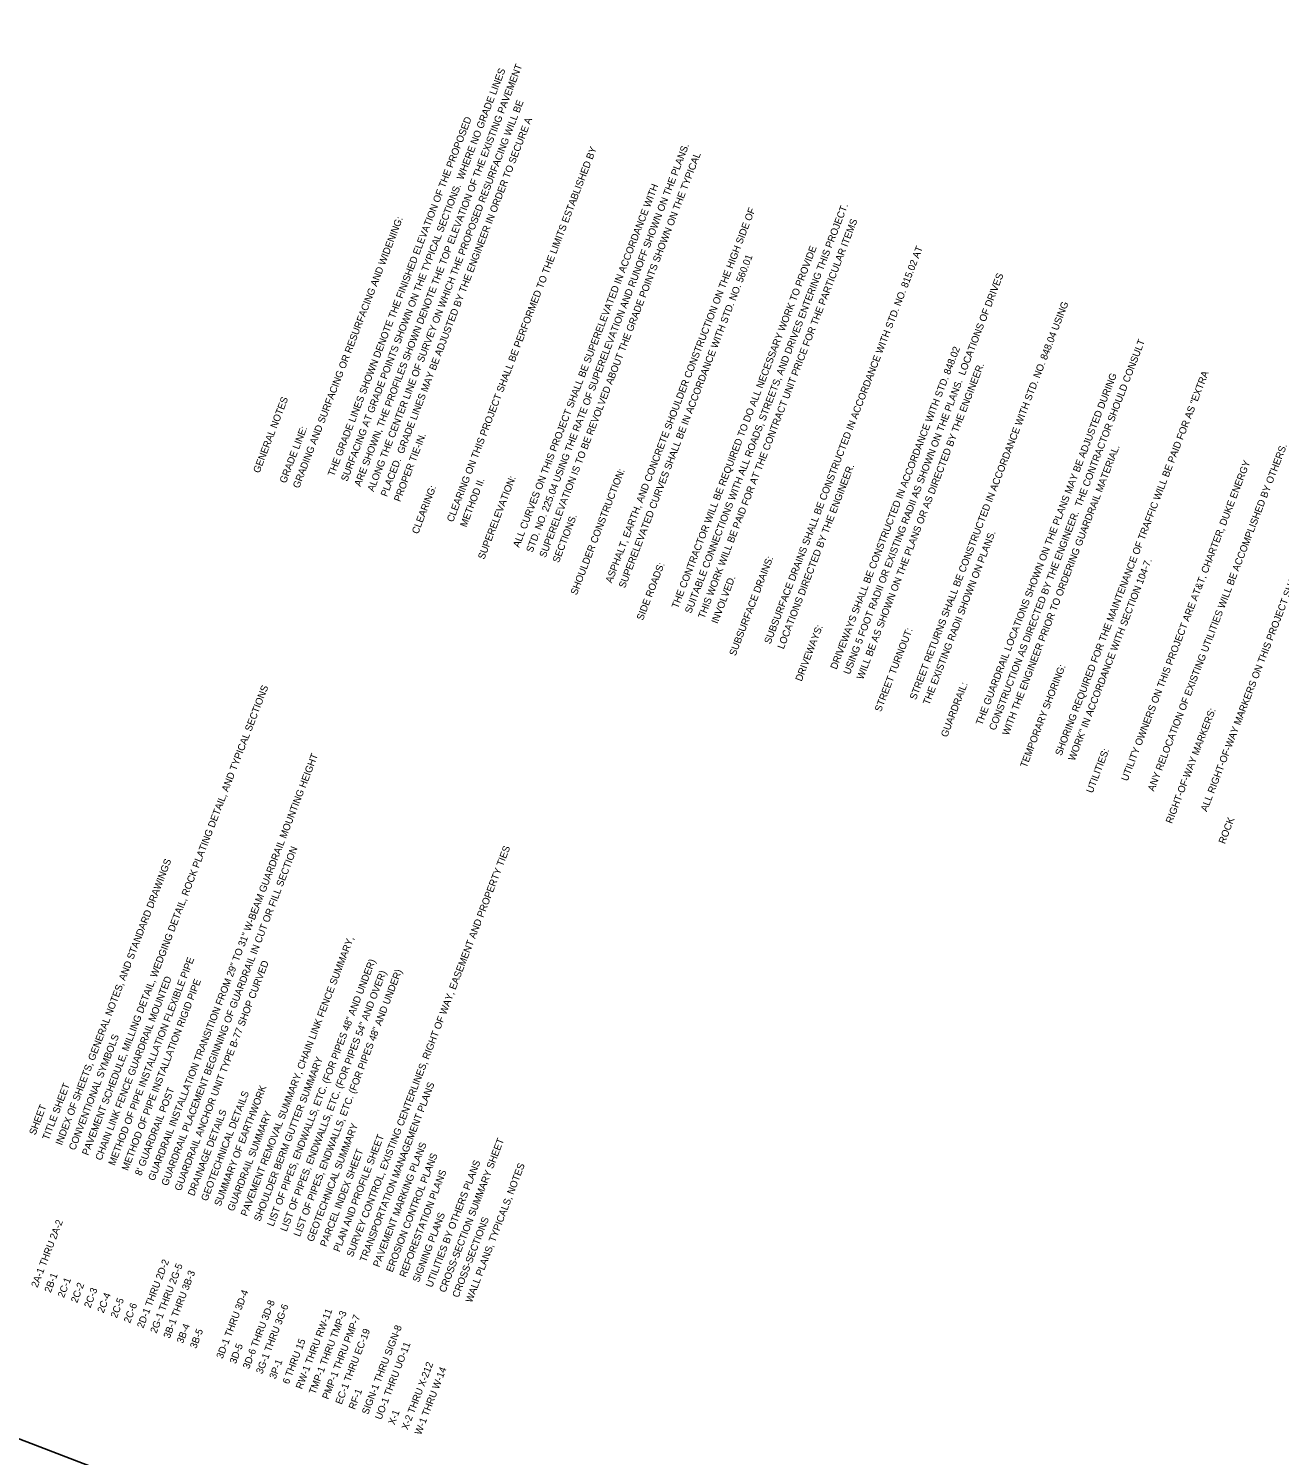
# Model space of a CAD drawing. Extents: x 1015221 to 1064345, y 619216 to 647967.
# Drawn here: x 1031915 to 1037502, y 630348 to 636795 of the extents above; entities that cross this region are included whole.
import ezdxf

# ---------------------------------------------------------------- set-up
doc = ezdxf.new("R2010")
doc.units = 0
doc.layers.add('Sheet Plan CELL', color=7, linetype='Continuous')
doc.layers.add('Sheet Plan Layout CELL', color=7, linetype='Continuous')

msp = doc.modelspace()

# ---------------------------------------------------------------- linework, layer by layer
at = {"layer": 'Sheet Plan CELL'}
msp.add_lwpolyline([(1033986, 642465.8), (1029682.3, 631264.1), (1037523.5, 628251.5), (1041827.2, 639453.2)], close=True, dxfattribs=at)

# ---------------------------------------------------------------- texts
at = {"layer": 'Sheet Plan Layout CELL'}
for s, height, p in [('         ARE SHOWN, THE PROFILES SHOWN DENOTE THE TOP ELEVATION OF THE EXISTING PAVEMENT                                                                                ', 31.9998, (1033375.6, 634623.4)), ('         SURFACING AT GRADE POINTS SHOWN ON THE TYPICAL SECTIONS.  WHERE NO GRADE LINES                                                                                 ', 31.9998, (1033315.8, 634646.3)), ('         ALONG THE CENTER LINE OF SURVEY ON WHICH THE PROPOSED RESURFACING WILL BE                                                                              ', 31.9998, (1033435.3, 634600.4)), ('         THE GRADE LINES SHOWN DENOTE THE FINISHED ELEVATION OF THE PROPOSED                                                                            ', 31.9998, (1033256.1, 634669.3)), ('         PLACED.  GRADE LINES MAY BE ADJUSTED BY THE ENGINEER IN ORDER TO SECURE A                                                                              ', 31.9998, (1033495, 634577.5)), ('         CLEARING ON THIS PROJECT SHALL BE PERFORMED TO THE LIMITS ESTABLISHED BY                                                                               ', 31.9998, (1033793.8, 634462.7)), ('         STD. NO. 225.04 USING THE RATE OF SUPERELEVATION AND RUNOFF SHOWN ON THE PLANS.                                                         ', 31.9998, (1034152.2, 634325)), ('         SUPERELEVATION IS TO BE REVOLVED ABOUT THE GRADE POINTS SHOWN ON THE TYPICAL                                                                           ', 31.9998, (1034211.9, 634302.1)), ('         ALL CURVES ON THIS PROJECT SHALL BE SUPERELEVATED IN ACCORDANCE WITH                                                                           ', 31.9998, (1034092.5, 634348)), ('         ASPHALT, EARTH, AND CONCRETE SHOULDER CONSTRUCTION ON THE HIGH SIDE OF                                                                         ', 31.9998, (1034510.7, 634187.3)), ('         SUITABLE CONNECTIONS WITH ALL ROADS, STREETS, AND DRIVES ENTERING THIS PROJECT.                                                                                ', 31.9998, (1034869.1, 634049.6)), ('GRADING AND SURFACING OR RESURFACING AND WIDENING:                                                                              ', 31.9998, (1033136.6, 634715.2)), ('         THIS WORK WILL BE PAID FOR AT THE CONTRACT UNIT PRICE FOR THE PARTICULAR ITEMS                                                                                 ', 31.9998, (1034928.9, 634026.6)), ('         THE CONTRACTOR WILL BE REQUIRED TO DO ALL NECESSARY WORK TO PROVIDE                                                                            ', 31.9998, (1034809.4, 634072.5)), ('         SUBSURFACE DRAINS SHALL BE CONSTRUCTED IN ACCORDANCE WITH STD. NO. 815.02 AT                                                                           ', 31.9998, (1035227.6, 633911.8)), ('         SUPERELEVATED CURVES SHALL BE IN ACCORDANCE WITH STD. NO. 560.01                 ', 32, (1034570.4, 634164.3)), ('         USING 5 FOOT RADII OR EXISTING RADII AS SHOWN ON THE PLANS.  LOCATIONS OF DRIVES                                                                               ', 31.9998, (1035586, 633774.1)), ('         STREET RETURNS SHALL BE CONSTRUCTED IN ACCORDANCE WITH STD. NO. 848.04 USING                                                                           ', 31.9998, (1035884.7, 633659.4)), ('         CONSTRUCTION AS DIRECTED BY THE ENGINEER.  THE CONTRACTOR SHOULD CONSULT                                                                               ', 31.9998, (1036243.2, 633521.6)), ('         DRIVEWAYS SHALL BE CONSTRUCTED IN ACCORDANCE WITH STD. 848.02                                                                          ', 31.9998, (1035526.3, 633797.1)), ('         WILL BE AS SHOWN ON THE PLANS OR AS DIRECTED BY THE ENGINEER.                                                                                  ', 31.9998, (1035645.8, 633751.2)), ('         THE GUARDRAIL LOCATIONS SHOWN ON THE PLANS MAY BE ADJUSTED DURING                                                                              ', 31.9998, (1036183.4, 633544.6)), ('         SHORING REQUIRED FOR THE MAINTENANCE OF TRAFFIC WILL BE PAID FOR AS "EXTRA                                                                             ', 31.9998, (1036541.9, 633406.9)), ('GENERAL NOTES', 32, (1032957.4, 634784.1)), ('GRADE LINE:                                                                             ', 32, (1033076.8, 634738.2)), ('         PROPER TIE-IN.                                                                                 ', 31.9998, (1033554.8, 634554.5)), ('         WITH THE ENGINEER PRIOR TO ORDERING GUARDRAIL MATERIAL.                                                                                ', 31.9998, (1036302.9, 633498.7)), ('         ANY RELOCATION OF EXISTING UTILITIES WILL BE ACCOMPLISHED BY OTHERS.                                                                           ', 31.9998, (1036960.1, 633246.2)), ('         LOCATIONS DIRECTED BY THE ENGINEER. ', 32, (1035287.3, 633888.9)), ('         UTILITY OWNERS ON THIS PROJECT ARE AT&T, CHARTER, DUKE ENERGY                                      ', 31.9998, (1036840.6, 633292.1)), ('         ALL RIGHT-OF-WAY MARKERS ON THIS PROJECT SHALL BE PLACED BY OTHERS.                                                                            ', 31.9998, (1037199.1, 633154.4)), ('         METHOD II.                                                                             ', 32, (1033853.5, 634439.8)), ('SUPERELEVATION:                                                                                 ', 32, (1033973, 634393.9)), ('SHOULDER CONSTRUCTION:                                                                                  ', 31.9998, (1034391.2, 634233.2)), ('CLEARING:                                                                               ', 32, (1033674.3, 634508.6)), ('         SECTIONS.                                                                              ', 32, (1034271.7, 634279.1)), ('         THE EXISTING RADII SHOWN ON PLANS.                                                                             ', 31.9998, (1035944.5, 633636.4)), ('SIDE ROADS:                                                                             ', 32, (1034689.9, 634118.4)), ('SUBSURFACE DRAINS:                                                                              ', 32, (1035108.1, 633957.8)), ('         WORK" IN ACCORDANCE WITH SECTION 104-7.                                                                                ', 31.9998, (1036601.6, 633383.9)), ('         INVOLVED.                                                                              ', 32, (1034988.6, 634003.7)), ('DRIVEWAYS:                                                                              ', 32, (1035406.8, 633843)), ('STREET TURNOUT:                                                                                 ', 32, (1035765.2, 633705.3)), ('TEMPORARY SHORING:                                                                              ', 32, (1036422.4, 633452.8)), ('PAVEMENT SCHEDULE, MILLING DETAIL, WEDGING DETAIL, ROCK PLATING DETAIL, AND TYPICAL SECTIONS', 32, (1032184.2, 631701.1)), ('GUARDRAIL:                                                                              ', 32, (1036064, 633590.5)), ('RIGHT-OF-WAY MARKERS:                                                                           ', 32, (1037079.6, 633200.3)), ('GUARDRAIL INSTALLATION TRANSITION FROM 29" TO 31" W-BEAM GUARDRAIL MOUNTING HEIGHT', 32, (1032483, 631586.4)), ('UTILITIES:                                                                              ', 32, (1036721.1, 633338)), ('ROCK                                                                            ', 32, (1037318.5, 633108.5)), ('GUARDRAIL PLACEMENT BEGINNING OF GUARDRAIL IN CUT OR FILL SECTION', 32, (1032542.7, 631563.4)), ('SURVEY CONTROL, EXISTING CENTERLINES, RIGHT OF WAY, EASEMENT AND PROPERTY TIES', 32, (1033379.1, 631242.1)), ('INDEX OF SHEETS, GENERAL NOTES, AND STANDARD DRAWINGS', 32, (1032064.8, 631747)), ('PAVEMENT REMOVAL SUMMARY, CHAIN LINK FENCE SUMMARY,', 32, (1032901.2, 631425.7)), ('METHOD OF PIPE INSTALLATION FLEXIBLE PIPE', 32, (1032303.7, 631655.2)), ('GUARDRAIL ANCHOR UNIT TYPE B-77 SHOP CURVED', 32, (1032602.4, 631540.4)), ('LIST OF PIPES, ENDWALLS, ETC. (FOR PIPES 48" AND UNDER)', 32, (1033020.6, 631379.8)), ('CHAIN LINK FENCE GUARDRAIL MOUNTED', 32, (1032244, 631678.2)), ('METHOD OF PIPE INSTALLATION RIGID PIPE', 32, (1032363.5, 631632.3)), ('LIST OF PIPES, ENDWALLS, ETC. (FOR PIPES 54" AND OVER)', 32, (1033080.4, 631356.8)), ('LIST OF PIPES, ENDWALLS, ETC. (FOR PIPES 48" AND UNDER)', 32, (1033140.1, 631333.9)), ('CONVENTIONAL SYMBOLS', 32, (1032124.5, 631724.1)), ('SHOULDER BERM GUTTER SUMMARY', 32, (1032960.9, 631402.7)), ('TITLE SHEET', 32, (1032005, 631770)), ("8' GUARDRAIL POST", 32, (1032423.2, 631609.3)), ('GEOTECHNICAL DETAILS', 32, (1032721.9, 631494.5)), ('SUMMARY OF EARTHWORK', 32, (1032781.7, 631471.6)), ('TRANSPORTATION MANAGEMENT PLANS', 32, (1033438.8, 631219.1)), ('SHEET', 32, (1031945.3, 631792.9)), ('DRAINAGE DETAILS', 32, (1032662.2, 631517.5)), ('GUARDRAIL SUMMARY', 32, (1032841.4, 631448.6)), ('GEOTECHNICAL SUMMARY', 32, (1033199.9, 631310.9)), ('PLAN AND PROFILE SHEET', 32, (1033319.3, 631265)), ('CROSS-SECTION SUMMARY SHEET', 32, (1033797.3, 631081.4)), ('PARCEL INDEX SHEET', 32, (1033259.6, 631288)), ('PAVEMENT MARKING PLANS', 32, (1033498.6, 631196.1)), ('EROSION CONTROL PLANS', 32, (1033558.3, 631173.2)), ('UTILITIES BY OTHERS PLANS', 32, (1033737.5, 631104.3)), ('WALL PLANS, TYPICALS, NOTES', 32, (1033916.8, 631035.5)), ('REFORESTATION PLANS', 32, (1033618.1, 631150.2)), ('2A-1 THRU 2A-2', 32, (1031954.7, 631103.7)), ('SIGNING PLANS', 32, (1033677.8, 631127.3)), ('CROSS-SECTIONS', 32, (1033857, 631058.4)), ('2D-1 THRU 2D-2', 32, (1032432.7, 630920.1)), ('2G-1 THRU 2G-5', 32, (1032492.4, 630897.1)), ('2B-1', 32, (1032014.5, 631080.7)), ('2C-1', 32, (1032074.2, 631057.8)), ('3B-1 THRU 3B-3', 32, (1032552.1, 630874.2)), ('2C-2', 32, (1032133.9, 631034.8)), ('2C-3', 32, (1032193.7, 631011.9)), ('2C-4', 32, (1032253.4, 630988.9)), ('3D-1 THRU 3D-4', 32, (1032791.1, 630782.4)), ('2C-5', 32, (1032313.2, 630966)), ('2C-6', 32, (1032372.9, 630943)), ('3D-6 THRU 3D-8', 32, (1032910.6, 630736.4)), ('3G-1 THRU 3G-6', 32, (1032970.3, 630713.5)), ('RW-1 THRU RW-11 ', 32, (1033149.6, 630644.6)), ('TMP-1 THRU TMP-3', 32, (1033209.3, 630621.7)), ('PMP-1 THRU PMP-7', 32, (1033269, 630598.7)), ('3B-4', 32, (1032611.9, 630851.2)), ('3B-5', 32, (1032671.6, 630828.3)), ('EC-1 THRU EC-19', 32, (1033328.8, 630575.8)), ('SIGN-1 THRU SIGN-8', 32, (1033448.3, 630529.9)), ('3D-5', 32, (1032850.8, 630759.4)), ('6 THRU 15', 32, (1033089.8, 630667.6)), ('UO-1 THRU UO-11', 32, (1033508, 630506.9)), ('3P-1', 32, (1033030.1, 630690.5)), ('X-2 THRU X-212', 32, (1033627.5, 630461)), ('W-1 THRU W-14', 32, (1033687.2, 630438.1)), ('RF-1', 32, (1033388.5, 630552.8)), ('X-1', 32, (1033567.8, 630484))]:
    msp.add_text(s, height=height, rotation=68.98302, dxfattribs=at).set_placement(p)

doc.saveas('drawing.dxf')
